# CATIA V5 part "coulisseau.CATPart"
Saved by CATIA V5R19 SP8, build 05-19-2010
Part number: coulisseau
Bounding box of the stored display mesh (mm): x -5 to 15, y -234.73 to -184.73, z -50 to 0
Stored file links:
  C:\Users\rcousturie\Desktop\EU_thinkMotion\iao\IAO_MMS_Groupe1\vduret\vduret\vduret\CATIA_disque\coulisseau.CATPart
  C:\Users\rcousturie\Desktop\EU_thinkMotion\iao\IAO_MMS_Groupe1\vduret\vduret\vduret\CATIA_disque\coulisse.CATPart
  C:\Users\rcousturie\Desktop\EU_thinkMotion\iao\IAO_MMS_Groupe1\vduret\vduret\vduret\CATIA_disque\vduret.CATProduct
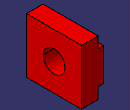
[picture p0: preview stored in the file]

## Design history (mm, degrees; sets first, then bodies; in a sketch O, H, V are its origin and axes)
External parameters (linked from other documents)
  External.largeur_rainure_coulisse = 30 mm
  External.largeur_coulisse = 60 mm
  External.diam_maneton = 20 mm
  External.epaisseur_rainure = 5 mm
Body1 (main body)
  Sketch1 on yz-plane, origin (0, 0, 0), H (0, 1, 0), V (0, 0, 1)
    point P1 (-234.7301, 0)
    line L1 (-234.7301, 0) -> (-184.7301, 0)
    line L2 (-184.7301, 0) -> (-184.7301, -50)
    line L3 (-184.7301, -50) -> (-234.7301, -50)
    line L4 (-234.7301, -50) -> (-234.7301, 0)
    length L2 = 50 {= External.largeur_coulisse -2*External.epaisseur_rainure}
    length L1 = 50 {= External.largeur_coulisse -2*External.epaisseur_rainure}
    coincidence: P1 H
    horizontal: L1 H, L3 H
    vertical: L2 V, L4 V
  Pad1: profile Sketch1, direction (1, 0, 0), length 15
  Sketch2 on start face of Pad1, origin (0, 0, 0), H (0, -1, 0), V (0, 0, 1)
    line L1 (184.7301, -10) -> (234.7301, -10)
    line L2 (234.7301, -10) -> (234.7301, -40)
    line L3 (234.7301, -40) -> (184.7301, -40)
    line L4 (184.7301, -40) -> (184.7301, -10)
    reference projected line E1 (184.7301, -60) -> (184.7301, 0) from edge [start face of Pad1 | face of Pad1 from Sketch1.L2]
    reference projected line E2 (234.7301, 0) -> (234.7301, -60) from edge [start face of Pad1 | face of Pad1 from Sketch1.L4]
    reference projected line E3 (190.9664, 0) -> (250.9664, 0) from edge [start face of Pad1 | face of Pad1 from Sketch1.L1]
    distance L1 L3 = 30 {= External.largeur_rainure_coulisse}
    distance L1 E3 = 10 {= (External.largeur_coulisse -10mm-External.largeur_rainure_coulisse )/2}
    horizontal: L1 H, L3 H
    vertical: L2 V, L4 V
    coincidence: L4 E1, L2 E2
  Pad2: profile Sketch2, direction (-1, 0, 0), length 5 {= External.epaisseur_rainure}
  Sketch3 on end face of Pad1, origin (15, 0, 0), H (0, 1, 0), V (0, 0, 1)
    circle A1 centre (-209.7301, -25) radius 10
    point P1 (-209.7301, -25)
    reference projected line E1 (-190.9664, 0) -> (-250.9664, 0) from edge [face of Pad1 from Sketch1.L1 | end face of Pad1]
    reference projected line E2 (-234.7301, 0) -> (-234.7301, -60) from edge [face of Pad1 from Sketch1.L4 | end face of Pad1]
    radius A1 = 10 {= External.diam_maneton /2}
    distance P1 E1 = 25 {= (External.largeur_coulisse -10mm)/2}
    distance P1 E2 = 25 {= (External.largeur_coulisse -10mm)/2}
  Pocket1: profile Sketch3, direction (-1, 0, 0), through (limit type 3)
Relations
  Sketch1.length(L2) = largeur_coulisse -2*`Paramètres externes\epaisseur_rainure` (deactivated)
  Sketch3.distance(P1 E2) = (`Paramètres externes\largeur_coulisse` -10mm)/2 (deactivated)
  Sketch3.distance(P1 E2) = (`Paramètres externes\largeur_coulisse` -10mm)/2 (deactivated)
